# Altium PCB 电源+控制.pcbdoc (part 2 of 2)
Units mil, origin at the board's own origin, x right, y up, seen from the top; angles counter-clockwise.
Board outline 7045 x 4395 mil, 2 copper layers (Top Layer, Bottom Layer); 84 components, 54 nets, 254 pads, 98 vias.
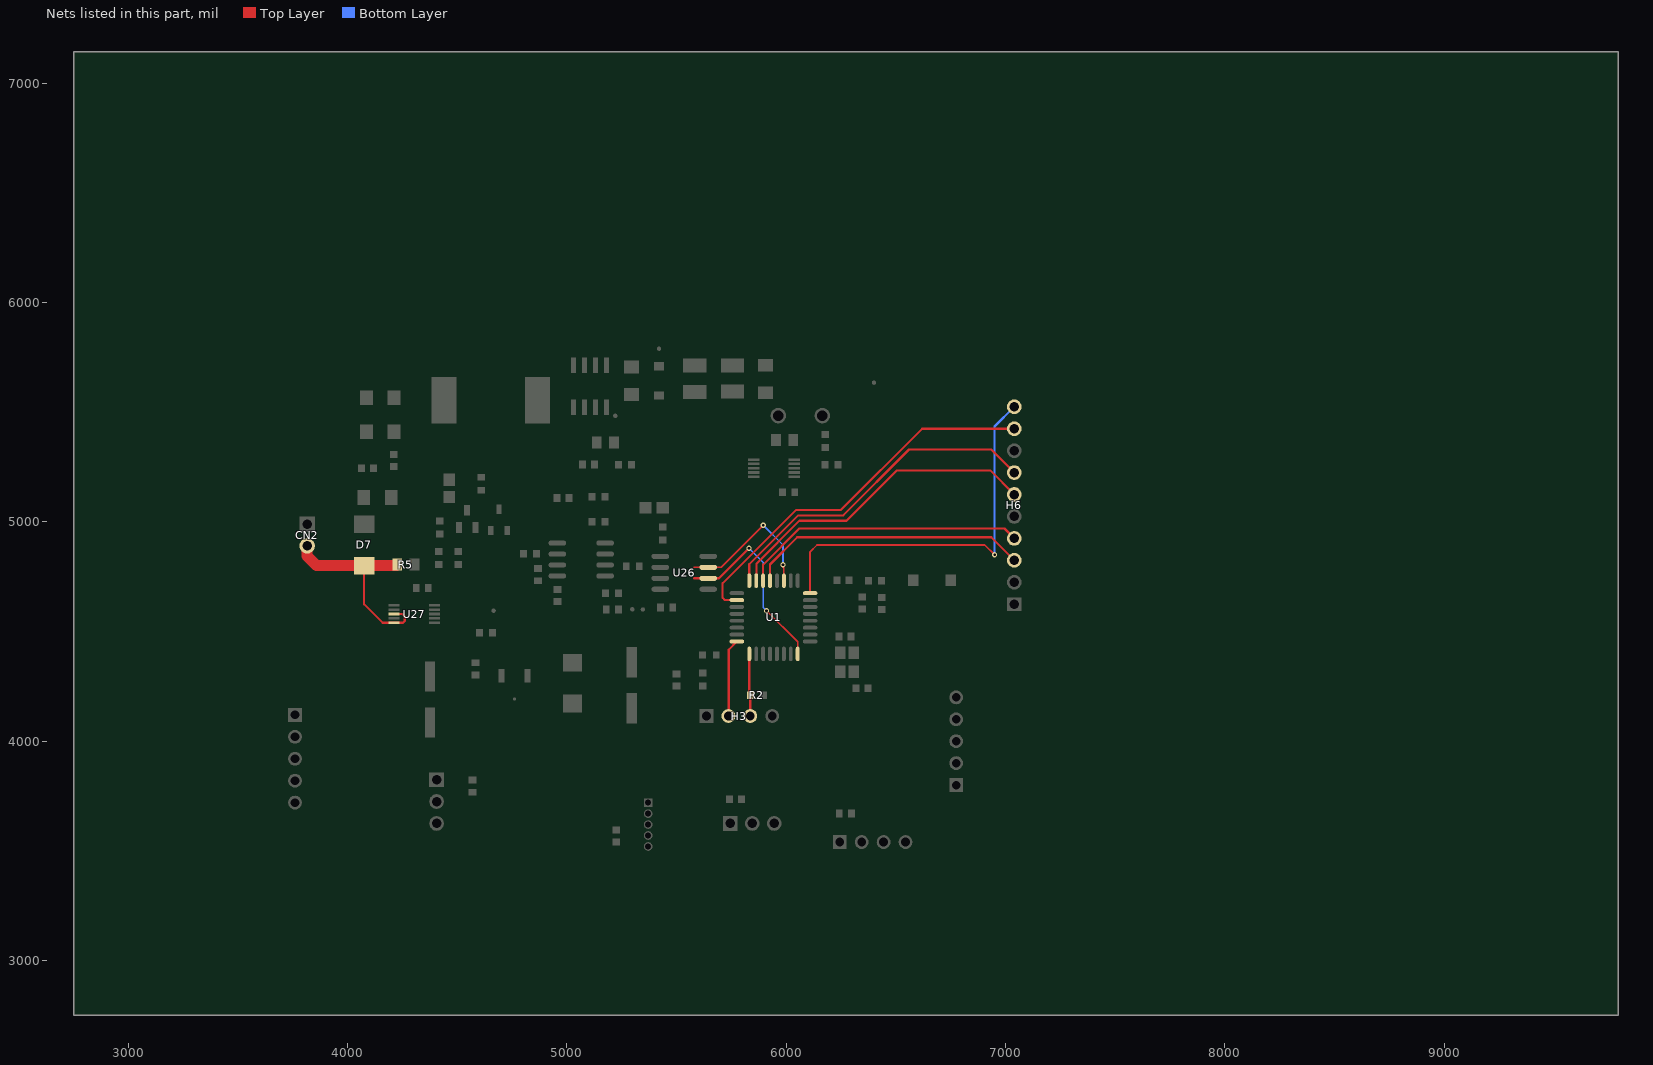
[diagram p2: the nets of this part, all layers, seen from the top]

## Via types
v1: diameter 24.02, hole 12.01, Top Layer to Bottom Layer, 98 vias

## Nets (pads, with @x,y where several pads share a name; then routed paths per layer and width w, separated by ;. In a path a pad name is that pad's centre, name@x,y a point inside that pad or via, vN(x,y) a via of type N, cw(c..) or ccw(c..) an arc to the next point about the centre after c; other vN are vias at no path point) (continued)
SPI_MOSI: U1.11 U26.3 | length 684.4
  Top Layer w8: 5579.15,4792.96 U26.3@5644.15,4792.96 5702.96,4792.96 v1(5895,4985) ; v1@5980,4800 5989.13,4790.87 U1.11@5989.13,4732.01
  Bottom Layer w8: v1(5895,4985) 5985,4895 v1(5985,4805)
SPI_SCK: U1.32 U26.2 | length 881.6
  Top Layer w8: v1(5910,4595) 6052.13,4452.87 U1.32@6052.13,4397.99
  Top Layer w10: 5579.15,4742.96 5624.15,4742.96 5692.96,4742.96 v1(5830,4880)
  Bottom Layer w8: v1(5830,4880) 5895,4815 5895,4610 v1(5910,4595)
SWCLK: H3.3 R2.2 U1.25 | length 284.8
  Top Layer w10: U1.25@5831.65,4397.99 5831.65,4214.42 R2.2@5836.08,4210 H3.3@5836.08,4115
SWDIO: H3.2 U1.24 | length 350.1
  Top Layer w10: H3.2@5737.77,4120 5737.77,4417.64 U1.24@5774.88,4454.76
SWITCH1: H6.3 U1.13 | length 1282.8
  Top Layer w10: U1.13@5926.14,4732.01 5926.14,4806.14 6050,4930 6935,4930 H6.3@7040,4825
SWITCH2: H6.4 U1.14 | length 1305.1
  Top Layer w10: U1.14@5894.65,4732.01 5894.65,4804.65 6060,4970 6995,4970 H6.4@7040,4925
SWITCH3: H6.6 U1.15 | length 1475.4
  Top Layer w10: U1.15@5863.15,4732.01 5865,4733.86 5865,4810 6060,5005 6275,5005 6505,5235 6930,5235 H6.6@7040,5125
SWITCH4: H6.7 U1.16 | length 1543.3
  Top Layer w10: U1.16@5831.65,4732.01 5831.65,4806.65 6055,5030 6260,5030 6560,5330 6935,5330 H6.7@7040,5225
SWITCH5: H6.9 U1.18 | length 1757.3
  Top Layer w10: U1.18@5774.88,4643.74 5720,4643.74 5710,4653.74 5710,4720 6045,5055 6250,5055 6620,5425 H6.9@7040,5425
SWITCH6: H6.10 U1.8 | length 1773.6
  Top Layer w8: U1.8@6108.9,4675.24 6108.9,4863.9 6140,4895 6905,4895 v1(6950,4850)
  Bottom Layer w10: v1(6950,4850) 6950,5435 H6.10@7040,5525
VBUS: CN2.2 D7.1 R5.2 U27.8 U27.10 | length 921.8
  Top Layer w10: D7.1@4073.22,4802.06 4075,4800.28 4075,4625 4159.38,4540.62 U27.10@4211.06,4540.62 4252.48,4540.62 4260,4548.14 4260,4570 4249.99,4580.01 U27.8@4211.06,4580.01
  Top Layer w50: CN2.2@3815,4865.79 3815,4845 3857.94,4802.06 4073.22,4802.06 R5.2@4222.44,4802.06
pads on no net: D6.2 OSC1.1 U27.3 U28.3

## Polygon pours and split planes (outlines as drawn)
PGND on Top Layer (solid, remove dead copper, pour order 6): 3015,6155 7730,6155 7730,3270 3015,3270
PGND on Bottom Layer (solid, remove dead copper, pour order 14): 3000,6245 7715,6245 7715,3360 3000,3360
GND on Top Layer (solid, remove dead copper, pour order 0): 6150.53,4877.34 6844.28,4877.34 6880,4844.01 6880,4510 7260.09,4510 7255.48,3929.7 7255.48,3492.05 7255,3415 5645,3425 5635,3415 5635,3550 5640,3555 5869.85,3555 5889.85,3575 5889.85,3680.14 5875,3695 5770,3695 5765,3700 5765,3795 5795,3825 6233.61,3825 6326.57,3732.05 6829.83,3732.05 6829.83,4145 6429.31,4145 6429.31,4525.28 6150.53,4525.28
GND on Bottom Layer (solid, remove dead copper, pour order 8): 3615,3770 4640,3770 4720,3850 4720,4504.14 5570,4504.14 5570,4055 5600,4025 5885,4025 5885,4265 6111.71,4265 6111.71,4536.39 7289.11,4537.3 7290,3375 3635,3375 3620,3360 3620,3760 3615,3765
GND on Top Layer (solid, remove dead copper, pour order 4): 4975,5150 4975,5070 4985,5060 5015,5060 5015,4890 5005,4880 4770,4880 4770,4775 4785,4760 4879.42,4760 4900,4739.42 4900,4665 5000,4665 5040,4705 5129.34,4705 5129.34,4565.66 5150,4545 5454.39,4545 5454.39,4670 5505,4670 5505,4922.8 5562.2,4980 5710,4980 5960,5230 6009.76,5230 6009.76,5064.76 5759.69,4814.69 5589.9,4814.69 5589.9,4650 5719.9,4520 5725,4520 5725,4450 5715,4440 5645,4440 5640,4435 5640,4285.32 5363.53,4285.32 4868.2,4260.46 4801.3,4260.46 4801.3,4347.84 4635,4347.84 4635,4890 4680,4935 4760,4935 4760,5150

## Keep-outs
Top Layer:
  region: 5321.6,4788.93 5406.07,4788.93 5410,4785 5410,4690 5450.31,4649.69 5450.31,4560 5146.22,4560 5146.22,4641.22 5308.78,4641.22 5308.78,4778.68 5321.46,4791.35 5321.46,4789.07
  region: 5210,5105 5352.92,5105 5363.59,5094.34 5363.59,4806.57 5355.14,4798.12 5195.77,4798.12 5190.34,4803.56 5190.34,5085.34
  region: 5790,5200 5920,5200 5705,4985 5590,4985 5585,4990 5790,5195
  region: 4895,3560 4895,3460 5400,3460 5420,3480 5420,3575 4910,3575
  region: 4165,4875 4275,4875 4275,4755 4290,4740 4290,4629.31 4304.59,4614.72 4393.22,4614.72 4408.26,4599.69 4395.43,4586.86 4395.43,4482.34 4435,4420 4290,4475 4259.59,4505.41 4259.59,4530.21 4207.92,4581.88 4118.12,4581.88 4075,4625 4075,4785
  region: 6612.64,5417.64 6220,5025 6220,4990 6315,4895 6929.23,4895 6995,4829.23 6995,4665 6990,4660 7080,4660 7090,4670 7090,5644.22 6995,5644.22 6995,5440 6990,5435 6630,5435
Bottom Layer:
  region: 4675,4685 4715,4685 4715,4650 4675,4650
  region: 6140,5460 6230.13,5460 6230.13,5401.5 6140,5401.5
  region: 7063.18,5645 7175,5645 7260,5560 7260,4545 6760,4545 6820,5300
  region: 5905,4675 5965,4675 5985,4655 5985,4597.82 6025,4557.82 5969.6,4502.41 5960,4502.41 5960,4620
  region: 4410,5045 4365,5045 4350,5030 4350,5025 4402.39,4972.61 4410,4980.22
Board Outline Layer:
  circle w1: c3970,4445 r137.8
  region: 4107.8,4445 cw(c3970,4445) 3832.2,4445 cw(c3970,4445)
  region: 4340,5815 4955,5815 4955,5275 4340,5275
  lines w10: 6948.82,3480 3650,3480 3650,5880 6954.34,5880 ; 6948.96,3480 6948.96,3717.03 7190,3717.03 7190,5644.3 6955,5644.3 6955,5880

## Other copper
Top Layer:
  drawing of 279 lines, arcs and shapes, not listed
  text "上下翻转，右边放排针，下面放蓝牙红外线和雷达，中间放芯片，左边放电源" at 7505,6775 h120
  text "信号" at 4350,3000 h120
Bottom Layer:
  region net DS3231: 3803.5,4116.06 3803.5,4124.06 cw(c3803.5,4139.06) 3791.5,4130.06 3791.5,4110.06 cw(c3803.5,4101.06)
  region net +3.3V: 6249.12,3586.5 6239.12,3586.5 cw(c6220.37,3586.5) 6231.62,3571.5 6256.62,3571.5 cw(c6267.87,3586.5)
  region net BLE_TX: 6377.27,3567.49 6371.61,3573.15 6371.09,3572.68 6370.5,3572.27 6369.85,3571.91 6369.14,3571.59 6368.39,3571.32 6367.58,3571.08 6365.84,3570.73 6363.94,3570.52 6361.94,3570.42 6358.77,3570.45 6349.14,3571.16 6344.46,3571.46 6342.87,3571.47 6342.15,3571.43 6375.55,3538.03 6375.59,3539.52 6375.43,3543.05 6374.62,3553.57 6374.53,3556.78 6374.58,3558.83 6374.73,3560.79 6375.01,3562.61 6375.2,3563.46 6375.43,3564.27 6375.71,3565.02 6376.03,3565.73 6376.39,3566.38 6376.8,3566.97
  region net BLE_RX: 6477.27,3567.49 6471.61,3573.15 6471.09,3572.68 6470.5,3572.27 6469.85,3571.91 6469.14,3571.59 6468.39,3571.32 6467.58,3571.08 6465.84,3570.73 6463.94,3570.52 6461.94,3570.42 6458.77,3570.45 6449.14,3571.16 6444.46,3571.46 6442.87,3571.47 6442.15,3571.43 6475.55,3538.03 6475.59,3539.52 6475.43,3543.05 6474.62,3553.57 6474.53,3556.78 6474.58,3558.83 6474.73,3560.79 6475.01,3562.61 6475.2,3563.46 6475.43,3564.27 6475.71,3565.02 6476.03,3565.73 6476.39,3566.38 6476.8,3566.97
  region net +3.3V: 5643.58,4161.08 5628.58,4161.08 cw(c5613.5,4161.08) 5617.33,4146.5 5654.83,4146.5 cw(c5658.65,4161.08)
  region net +3.3V: 5672.88,4067.59 5683.48,4078.2 cw(c5723.26,4117.98) 5667.57,4110.02 5641.06,4083.5 cw(c5633.1,4027.82)
  region net LIGHT_ADC: 4450.92,3621 4450.92,3629 4450.17,3629.05 4449.41,3629.18 4448.64,3629.4 4447.87,3629.69 4447.09,3630.06 4446.31,3630.5 4445.53,3631 4443.95,3632.17 4442.37,3633.54 4440.01,3635.88 4436.18,3640.22 4429.89,3647.68 4428.07,3649.57 4427.5,3650.1 4427.5,3599.9 4428.66,3601.01 4430.54,3603.05 4437.69,3611.56 4440.8,3614.93 4442.37,3616.46 4443.95,3617.83 4445.53,3619 4446.31,3619.5 4447.09,3619.94 4447.87,3620.31 4448.64,3620.6 4449.41,3620.82 4450.17,3620.95
  region net INFRARED-RAY: 5849,3665 5841,3665 5840.95,3664.26 5840.82,3663.55 5840.6,3662.86 5840.31,3662.19 5839.94,3661.54 5839.5,3660.9 5839,3660.29 5838.45,3659.69 5837.83,3659.1 5836.46,3657.97 5834.93,3656.88 5832.43,3655.32 5825.42,3651.33 5823.05,3649.81 5821.64,3648.77 5821.01,3648.23 5820.43,3647.69 5819.9,3647.13 5870.1,3647.13 5869.57,3647.69 5868.99,3648.23 5867.68,3649.29 5866.19,3650.32 5862.87,3652.32 5856.71,3655.83 5854.28,3657.42 5852.83,3658.53 5852.17,3659.1 5851.55,3659.69 5851,3660.29 5850.5,3660.9 5850.06,3661.54 5849.69,3662.19 5849.4,3662.86 5849.18,3663.55 5849.05,3664.26
  region net 170V: 6213.04,5470 6213.04,5500 6211.39,5500.07 6209.73,5500.26 6208.07,5500.57 6206.4,5500.99 6204.73,5501.52 6202.26,5502.48 6199.82,5503.62 6197.44,5504.91 6195.14,5506.33 6192.21,5508.36 6189.5,5510.49 6188.24,5511.57 6188.24,5458.43 6190.83,5460.58 6193.65,5462.68 6196.66,5464.63 6199.02,5465.97 6201.44,5467.16 6203.9,5468.18 6205.56,5468.76 6207.23,5469.23 6208.9,5469.6 6210.56,5469.85 6212.22,5469.98
  region net SWITCH6: 7004.25,5496.32 7011.32,5489.25 7012.79,5490.63 7013.74,5491.41 7014.66,5492.09 7015.55,5492.67 7016.42,5493.16 7017.27,5493.56 7018.11,5493.88 7018.94,5494.13 7019.76,5494.3 7020.57,5494.41 7021.38,5494.46 7022.18,5494.45 7022.99,5494.4 7024.22,5494.25 7025.89,5493.92 7031.38,5492.57 7033.99,5492.04 7036.26,5491.73 7038.09,5491.58 7040.03,5491.53 7042.1,5491.6 7006.6,5527.1 7006.53,5525.03 7006.58,5523.09 7006.73,5521.26 7007.04,5518.99 7007.57,5516.38 7008.92,5510.89 7009.25,5509.22 7009.4,5507.99 7009.45,5507.18 7009.46,5506.38 7009.41,5505.57 7009.3,5504.76 7009.13,5503.94 7008.88,5503.11 7008.56,5502.27 7008.16,5501.42 7007.67,5500.55 7007.09,5499.66 7006.41,5498.74 7005.63,5497.79
  region net COLON2: 7068.68,5289.25 7075.75,5296.32 7074.37,5297.79 7073.59,5298.74 7072.91,5299.66 7072.33,5300.55 7071.84,5301.42 7071.44,5302.27 7071.12,5303.11 7070.87,5303.94 7070.7,5304.76 7070.59,5305.57 7070.54,5306.38 7070.55,5307.18 7070.6,5307.99 7070.75,5309.22 7071.08,5310.89 7072.43,5316.38 7072.96,5318.99 7073.27,5321.26 7073.42,5323.09 7073.47,5325.03 7073.4,5327.1 7037.9,5291.6 7039.97,5291.53 7041.91,5291.58 7043.74,5291.73 7046.01,5292.04 7048.62,5292.57 7054.11,5293.92 7055.78,5294.25 7057.01,5294.4 7057.82,5294.45 7058.62,5294.46 7059.43,5294.41 7060.24,5294.3 7061.06,5294.13 7061.89,5293.88 7062.73,5293.56 7063.58,5293.16 7064.45,5292.67 7065.34,5292.09 7066.26,5291.41 7067.21,5290.63
  region net COLON1: 7068.68,4989.25 7075.75,4996.32 7074.37,4997.79 7073.59,4998.74 7072.91,4999.66 7072.33,5000.55 7071.84,5001.42 7071.44,5002.27 7071.12,5003.11 7070.87,5003.94 7070.7,5004.76 7070.59,5005.57 7070.54,5006.38 7070.55,5007.18 7070.6,5007.99 7070.75,5009.22 7071.08,5010.89 7072.43,5016.38 7072.96,5018.99 7073.27,5021.26 7073.42,5023.09 7073.47,5025.03 7073.4,5027.1 7037.9,4991.6 7039.97,4991.53 7041.91,4991.58 7043.74,4991.73 7046.01,4992.04 7048.62,4992.57 7054.11,4993.92 7055.78,4994.25 7057.01,4994.4 7057.82,4994.45 7058.62,4994.46 7059.43,4994.41 7060.24,4994.3 7061.06,4994.13 7061.89,4993.88 7062.73,4993.56 7063.58,4993.16 7064.45,4992.67 7065.34,4992.09 7066.26,4991.41 7067.21,4990.63
  region net 170V: 6994.44,4740 6994.44,4710 6995.9,4709.94 6997.4,4709.77 6998.95,4709.5 7000.52,4709.13 7002.9,4708.42 7005.29,4707.52 7007.65,4706.48 7009.95,4705.32 7012.16,4704.05 7014.23,4702.71 7016.15,4701.32 7017.87,4699.9 7017.87,4750.1 7016.15,4748.68 7014.23,4747.29 7012.16,4745.95 7009.95,4744.68 7007.65,4743.52 7005.29,4742.48 7002.9,4741.58 7000.52,4740.87 6998.95,4740.5 6997.4,4740.23 6995.9,4740.06
  region net +5V: 6724.5,4089.85 6738.65,4075.71 6739.06,4076.1 6739.48,4076.45 6739.91,4076.76 6740.36,4077.04 6740.82,4077.29 6741.29,4077.5 6741.77,4077.69 6742.26,4077.84 6742.77,4077.97 6743.28,4078.06 6743.8,4078.13 6744.88,4078.2 6745.99,4078.16 6747.13,4078.04 6748.3,4077.84 6750.11,4077.4 6751.98,4076.82 6755.18,4075.62 6764.44,4071.62 6767.73,4070.33 6770.31,4069.49 6772.2,4069.01 6773.43,4068.77 6774.64,4068.61 6775.82,4068.54 6776.97,4068.57 6743.57,4101.97 6743.49,4101.35 6743.33,4100.75 6743.11,4100.2 6742.82,4099.67 6742.47,4099.18 6742.06,4098.71 6741.6,4098.27 6741.09,4097.86 6740.53,4097.47 6739.3,4096.74 6737.93,4096.07 6735.7,4095.16 6730.23,4093.14 6728.04,4092.19 6726.71,4091.49 6726.09,4091.12 6725.52,4090.72 6724.99,4090.3
  region net I2C1_SDA: 4453.02,4574.9 4460.1,4581.98 4459.71,4582.39 4459.35,4582.84 4459.03,4583.32 4458.73,4583.83 4458.46,4584.35 4458,4585.46 4457.64,4586.62 4457.36,4587.81 4457.16,4589 4456.98,4590.75 4444.25,4578.02 4446,4577.84 4447.19,4577.64 4448.38,4577.36 4449.54,4577 4450.65,4576.54 4451.17,4576.27 4451.68,4575.97 4452.16,4575.65 4452.61,4575.29
  region net I2C1_SCL: 4461.35,4635 4461.35,4645 4460.78,4645.02 4460.21,4645.09 4459.64,4645.2 4459.08,4645.34 4458.51,4645.53 4457.41,4645.98 4456.33,4646.54 4455.29,4647.19 4454.3,4647.89 4452.94,4649.01 4452.94,4630.99 4454.3,4632.11 4455.29,4632.81 4456.33,4633.46 4457.41,4634.02 4458.51,4634.47 4459.08,4634.66 4459.64,4634.8 4460.21,4634.91 4460.78,4634.98
  region net I2C1_SCL: 5701.98,4630.1 5694.9,4623.02 5695.29,4622.61 5695.65,4622.16 5695.97,4621.68 5696.27,4621.17 5696.54,4620.65 5697,4619.54 5697.36,4618.38 5697.64,4617.19 5697.84,4616 5698.02,4614.25 5710.75,4626.98 5709,4627.16 5707.81,4627.36 5706.62,4627.64 5705.46,4628 5704.35,4628.46 5703.83,4628.73 5703.32,4629.03 5702.84,4629.35 5702.39,4629.71
  region net I2C1_SCL: 5730.05,4618.07 5724.39,4623.73 5723.7,4623.2 5722.94,4622.89 5722.12,4622.77 5721.25,4622.82 5720.32,4623.01 5719.36,4623.31 5717.35,4624.17 5713.19,4626.12 5712.17,4626.5 5711.16,4626.79 5710.19,4626.96 5709.25,4626.98 5721.98,4614.25 5722.3,4615.17 5723.03,4615.79 5724.07,4616.2 5726.63,4616.72 5727.93,4617.01 5729.11,4617.43
  region net I2C1_SDA: 5693.65,4550 5693.65,4540 5694.22,4539.98 5694.79,4539.91 5695.36,4539.8 5695.92,4539.66 5696.49,4539.47 5697.59,4539.02 5698.67,4538.46 5699.71,4537.81 5700.7,4537.11 5702.06,4535.99 5702.06,4554.01 5700.7,4552.89 5699.71,4552.19 5698.67,4551.54 5697.59,4550.98 5696.49,4550.53 5695.92,4550.34 5695.36,4550.2 5694.79,4550.09 5694.22,4550.02
  region net I2C1_SDA: 5721.89,4556.23 5716.23,4561.89 5714.23,4559.74 5713.49,4558.97 5713.11,4558.62 5712.72,4558.3 5712.31,4558 5711.88,4557.74 5711.42,4557.5 5710.94,4557.31 5710.42,4557.16 5709.85,4557.05 5709.25,4556.98 5721.98,4544.25 5721.99,4544.89 5721.94,4545.59 5721.73,4547.16 5721.16,4550.59 5720.97,4552.29 5720.94,4553.09 5720.97,4553.85 5721.07,4554.55 5721.25,4555.19 5721.52,4555.76
  region net SWITCH6: 6955,4866.35 6945,4866.35 6944.98,4865.78 6944.91,4865.21 6944.8,4864.64 6944.66,4864.08 6944.47,4863.51 6944.02,4862.41 6943.46,4861.33 6942.81,4860.29 6942.11,4859.3 6940.99,4857.94 6959.01,4857.94 6957.89,4859.3 6957.19,4860.29 6956.54,4861.33 6955.98,4862.41 6955.53,4863.51 6955.34,4864.08 6955.2,4864.64 6955.09,4865.21 6955.02,4865.78
  region net COLON2: 6685,4141.35 6675,4141.35 6674.98,4140.78 6674.91,4140.21 6674.8,4139.64 6674.66,4139.08 6674.47,4138.51 6674.02,4137.41 6673.46,4136.33 6672.81,4135.29 6672.11,4134.3 6670.99,4132.94 6689.01,4132.94 6687.89,4134.3 6687.19,4135.29 6686.54,4136.33 6685.98,4137.41 6685.53,4138.51 6685.34,4139.08 6685.2,4139.64 6685.09,4140.21 6685.02,4140.78
  region net POWER: 5754.9,4711.98 5761.98,4704.9 5762.57,4705.37 5763.25,4705.66 5763.99,4705.81 5764.79,4705.82 5765.64,4705.73 5766.53,4705.54 5768.41,4704.97 5772.25,4703.62 5773.18,4703.35 5774.08,4703.14 5774.94,4703.03 5775.75,4703.02 5763.02,4715.75 5762.7,4714.82 5761.97,4714.21 5760.92,4713.81 5758.35,4713.31 5757.03,4713.03 5755.85,4712.62
  region net POWER: 4378.02,4989.9 4385.1,4996.98 4384.71,4997.39 4384.35,4997.84 4384.03,4998.32 4383.73,4998.83 4383.46,4999.35 4383,5000.46 4382.64,5001.62 4382.36,5002.81 4382.16,5004 4381.98,5005.75 4369.25,4993.02 4371,4992.84 4372.19,4992.64 4373.38,4992.36 4374.54,4992 4375.65,4991.54 4376.17,4991.27 4376.68,4990.97 4377.16,4990.65 4377.61,4990.29
  region net +5V: 4828.02,4769.9 4835.1,4776.98 4834.71,4777.39 4834.35,4777.84 4834.03,4778.32 4833.73,4778.83 4833.46,4779.35 4833,4780.46 4832.64,4781.62 4832.36,4782.81 4832.16,4784 4831.98,4785.75 4819.25,4773.02 4821,4772.84 4822.19,4772.64 4823.38,4772.36 4824.54,4772 4825.65,4771.54 4826.17,4771.27 4826.68,4770.97 4827.16,4770.65 4827.61,4770.29
  region net BLE_TX: 6069.39,4813.73 6063.73,4819.39 6063.23,4818.92 6062.71,4818.53 6062.19,4818.19 6061.65,4817.92 6061.11,4817.69 6060.55,4817.51 6059.98,4817.38 6059.4,4817.27 6058.2,4817.14 6054.95,4817.02 6054.25,4816.98 6066.98,4804.25 6067.11,4807.58 6067.2,4808.81 6067.27,4809.4 6067.38,4809.98 6067.51,4810.55 6067.69,4811.11 6067.92,4811.65 6068.19,4812.19 6068.53,4812.71 6068.92,4813.23
  region net BLE_RX: 6034.39,4813.73 6028.73,4819.39 6028.23,4818.92 6027.71,4818.53 6027.19,4818.19 6026.65,4817.92 6026.11,4817.69 6025.55,4817.51 6024.98,4817.38 6024.4,4817.27 6023.2,4817.14 6019.95,4817.02 6019.25,4816.98 6031.98,4804.25 6032.11,4807.58 6032.2,4808.81 6032.27,4809.4 6032.38,4809.98 6032.51,4810.55 6032.69,4811.11 6032.92,4811.65 6033.19,4812.19 6033.53,4812.71 6033.92,4813.23
  region net SPI_MOSI: 5989,4821.35 5981,4821.35 5980.97,4820.66 5980.89,4820.02 5980.75,4819.41 5980.57,4818.84 5980.34,4818.29 5980.08,4817.77 5979.77,4817.27 5979.44,4816.79 5978.68,4815.85 5976.46,4813.46 5975.99,4812.94 5994.01,4812.94 5991.74,4815.39 5990.93,4816.32 5990.56,4816.79 5990.23,4817.27 5989.92,4817.77 5989.66,4818.29 5989.43,4818.84 5989.25,4819.41 5989.11,4820.02 5989.03,4820.66
  region net SPI_MOSI: 5903.73,4970.61 5909.39,4976.27 5908.92,4976.77 5908.53,4977.29 5908.19,4977.81 5907.92,4978.35 5907.69,4978.89 5907.51,4979.45 5907.38,4980.02 5907.27,4980.6 5907.14,4981.8 5907.02,4985.05 5906.98,4985.75 5894.25,4973.02 5897.58,4972.89 5898.81,4972.8 5899.4,4972.73 5899.98,4972.62 5900.55,4972.49 5901.11,4972.31 5901.65,4972.08 5902.19,4971.81 5902.71,4971.47 5903.23,4971.08
  region net SPI_SCK: 5838.73,4865.61 5844.39,4871.27 5843.92,4871.77 5843.53,4872.29 5843.19,4872.81 5842.92,4873.35 5842.69,4873.89 5842.51,4874.45 5842.38,4875.02 5842.27,4875.6 5842.14,4876.8 5842.02,4880.05 5841.98,4880.75 5829.25,4868.02 5832.58,4867.89 5833.81,4867.8 5834.4,4867.73 5834.98,4867.62 5835.55,4867.49 5836.11,4867.31 5836.65,4867.08 5837.19,4866.81 5837.71,4866.47 5838.23,4866.08
  region net SPI_SCK: 5901.27,4609.39 5895.61,4603.73 5896.08,4603.23 5896.47,4602.71 5896.81,4602.19 5897.08,4601.65 5897.31,4601.11 5897.49,4600.55 5897.62,4599.98 5897.73,4599.4 5897.86,4598.2 5897.98,4594.95 5898.02,4594.25 5910.75,4606.98 5907.42,4607.11 5906.19,4607.2 5905.6,4607.27 5905.02,4607.38 5904.45,4607.51 5903.89,4607.69 5903.35,4607.92 5902.81,4608.19 5902.29,4608.53 5901.77,4608.92
  region net I2C1_SCL: 5603.73,5000.61 5609.39,5006.27 5608.92,5006.77 5608.53,5007.29 5608.19,5007.81 5607.92,5008.35 5607.69,5008.89 5607.51,5009.45 5607.38,5010.02 5607.27,5010.6 5607.14,5011.8 5607.02,5015.05 5606.98,5015.75 5594.25,5003.02 5597.58,5002.89 5598.81,5002.8 5599.4,5002.73 5599.98,5002.62 5600.55,5002.49 5601.11,5002.31 5601.65,5002.08 5602.19,5001.81 5602.71,5001.47 5603.23,5001.08
  region net I2C1_SDA: 5616,5073.65 5624,5073.65 5624.03,5074.34 5624.11,5074.98 5624.25,5075.59 5624.43,5076.16 5624.66,5076.71 5624.92,5077.23 5625.23,5077.73 5625.56,5078.21 5626.32,5079.15 5628.54,5081.54 5629.01,5082.06 5610.99,5082.06 5613.26,5079.61 5614.07,5078.68 5614.44,5078.21 5614.77,5077.73 5615.08,5077.23 5615.34,5076.71 5615.57,5076.16 5615.75,5075.59 5615.89,5074.98 5615.97,5074.34
  region net DS3231: 5831.27,4494.39 5825.61,4488.73 5826.08,4488.23 5826.47,4487.71 5826.81,4487.19 5827.08,4486.65 5827.31,4486.11 5827.49,4485.55 5827.62,4484.98 5827.73,4484.4 5827.86,4483.2 5827.98,4479.95 5828.02,4479.25 5840.75,4491.98 5837.42,4492.11 5836.19,4492.2 5835.6,4492.27 5835.02,4492.38 5834.45,4492.51 5833.89,4492.69 5833.35,4492.92 5832.81,4493.19 5832.29,4493.53 5831.77,4493.92
  region net RADER_TX: 5956,4648.65 5964,4648.65 5964.03,4649.34 5964.11,4649.98 5964.25,4650.59 5964.43,4651.16 5964.66,4651.71 5964.92,4652.23 5965.23,4652.73 5965.56,4653.21 5966.32,4654.15 5968.54,4656.54 5969.01,4657.06 5950.99,4657.06 5953.26,4654.61 5954.07,4653.68 5954.44,4653.21 5954.77,4652.73 5955.08,4652.23 5955.34,4651.71 5955.57,4651.16 5955.75,4650.59 5955.89,4649.98 5955.97,4649.34
  region net RADER_TX: 5544.39,4128.73 5538.73,4134.39 5538.4,4133.99 5538.1,4133.53 5537.84,4133.01 5537.39,4131.86 5536.57,4129.45 5536.34,4128.9 5536.09,4128.39 5535.81,4127.94 5535.49,4127.57 5535.13,4127.27 5534.72,4127.07 5534.25,4126.98 5546.98,4114.25 5546.97,4115.13 5546.82,4116.05 5546.57,4117 5545.86,4118.98 5544.2,4122.97 5543.87,4123.93 5543.62,4124.86 5543.47,4125.75 5543.45,4126.59 5543.58,4127.37 5543.89,4128.09
  region net RADER: 6054,4111.35 6046,4111.35 6045.97,4110.66 6045.89,4110.02 6045.75,4109.41 6045.57,4108.84 6045.34,4108.29 6045.08,4107.77 6044.77,4107.27 6044.44,4106.79 6043.68,4105.85 6041.46,4103.46 6040.99,4102.94 6059.01,4102.94 6056.74,4105.39 6055.93,4106.32 6055.56,4106.79 6055.23,4107.27 6054.92,4107.77 6054.66,4108.29 6054.43,4108.84 6054.25,4109.41 6054.11,4110.02 6054.03,4110.66
  region net RADER_RX: 6094,4086.35 6086,4086.35 6085.97,4085.66 6085.89,4085.02 6085.75,4084.41 6085.57,4083.84 6085.34,4083.29 6085.08,4082.77 6084.77,4082.27 6084.44,4081.79 6083.68,4080.85 6081.46,4078.46 6080.99,4077.94 6099.01,4077.94 6096.74,4080.39 6095.93,4081.32 6095.56,4081.79 6095.23,4082.27 6094.92,4082.77 6094.66,4083.29 6094.43,4083.84 6094.25,4084.41 6094.11,4085.02 6094.03,4085.66
  region net RADER_RX: 6086,4368.65 6094,4368.65 6094.03,4369.34 6094.11,4369.98 6094.25,4370.59 6094.43,4371.16 6094.66,4371.71 6094.92,4372.23 6095.23,4372.73 6095.56,4373.21 6096.32,4374.15 6098.54,4376.54 6099.01,4377.06 6080.99,4377.06 6083.26,4374.61 6084.07,4373.68 6084.44,4373.21 6084.77,4372.73 6085.08,4372.23 6085.34,4371.71 6085.57,4371.16 6085.75,4370.59 6085.89,4369.98 6085.97,4369.34
  region net RADER: 6046,4498.65 6054,4498.65 6053.97,4499.4 6053.89,4500.09 6053.76,4500.72 6053.44,4501.83 6052.96,4503.25 6052.85,4503.69 6052.78,4504.12 6052.77,4504.56 6052.83,4505.01 6052.97,4505.47 6053.21,4505.96 6053.55,4506.49 6054.01,4507.06 6035.99,4507.06 6036.52,4506.54 6037.14,4506.04 6038.61,4505.08 6041.94,4503.21 6043.49,4502.23 6044.18,4501.71 6044.79,4501.16 6045.29,4500.59 6045.67,4499.98 6045.92,4499.34
  region net INFRARED-RAY: 5906,4503.65 5914,4503.65 5914.03,4504.34 5914.11,4504.98 5914.25,4505.59 5914.43,4506.16 5914.66,4506.71 5914.92,4507.23 5915.23,4507.73 5915.56,4508.21 5916.32,4509.15 5918.54,4511.54 5919.01,4512.06 5900.99,4512.06 5903.26,4509.61 5904.07,4508.68 5904.44,4508.21 5904.77,4507.73 5905.08,4507.23 5905.34,4506.71 5905.57,4506.16 5905.75,4505.59 5905.89,4504.98 5905.97,4504.34
  region net LIGHT_ADC: 5848.73,4535.61 5854.39,4541.27 5853.92,4541.77 5853.53,4542.29 5853.19,4542.81 5852.92,4543.35 5852.69,4543.89 5852.51,4544.45 5852.38,4545.02 5852.27,4545.6 5852.14,4546.8 5852.02,4550.05 5851.98,4550.75 5839.25,4538.02 5842.58,4537.89 5843.81,4537.8 5844.4,4537.73 5844.98,4537.62 5845.55,4537.49 5846.11,4537.31 5846.65,4537.08 5847.19,4536.81 5847.71,4536.47 5848.23,4536.08
  region net +3.3V: 6028.65,4557.5 6028.65,4542.5 6031.58,4542.6 6032.65,4542.6 6033.17,4542.58 6033.68,4542.53 6034.18,4542.44 6034.67,4542.32 6035.16,4542.16 6035.64,4541.96 6036.11,4541.69 6036.59,4541.38 6037.06,4540.99 6037.06,4559.01 6036.59,4558.62 6036.11,4558.31 6035.64,4558.04 6035.16,4557.84 6034.67,4557.68 6034.18,4557.56 6033.68,4557.47 6033.17,4557.42 6032.12,4557.39 6029.27,4557.49
  region net +3.3V: 6061.35,4545 6061.35,4555 6060.78,4555.02 6060.21,4555.09 6059.64,4555.2 6059.08,4555.34 6058.51,4555.53 6057.41,4555.98 6056.33,4556.54 6055.29,4557.19 6054.3,4557.89 6052.94,4559.01 6052.94,4540.99 6054.3,4542.11 6055.29,4542.81 6056.33,4543.46 6057.41,4544.02 6058.51,4544.47 6059.08,4544.66 6059.64,4544.8 6060.21,4544.91 6060.78,4544.98
  region net +5V: 6018.65,5180 6018.65,5170 6019.22,5169.98 6019.79,5169.91 6020.36,5169.8 6020.92,5169.66 6021.49,5169.47 6022.59,5169.02 6023.67,5168.46 6024.71,5167.81 6025.7,5167.11 6027.06,5165.99 6027.06,5184.01 6025.7,5182.89 6024.71,5182.19 6023.67,5181.54 6022.59,5180.98 6021.49,5180.53 6020.92,5180.34 6020.36,5180.2 6019.79,5180.09 6019.22,5180.02
  region net +3.3V: 6304.37,4246.5 6304.37,4236.5 6304.91,4236.48 6305.41,4236.41 6305.87,4236.3 6306.29,4236.16 6306.69,4235.98 6307.06,4235.76 6307.41,4235.52 6307.75,4235.25 6308.41,4234.64 6310.16,4232.87 6310.57,4232.5 6310.57,4250.51 6309.77,4249.76 6308.08,4248.05 6307.75,4247.75 6307.41,4247.48 6307.06,4247.24 6306.69,4247.03 6306.29,4246.85 6305.87,4246.7 6305.41,4246.59 6304.91,4246.52
  region net $3N2629: 4681.35,4590 4681.35,4600 4680.78,4600.02 4680.21,4600.09 4679.64,4600.2 4679.08,4600.34 4678.51,4600.53 4677.41,4600.98 4676.33,4601.54 4675.29,4602.19 4674.3,4602.89 4672.94,4604.01 4672.94,4585.99 4674.3,4587.11 4675.29,4587.81 4676.33,4588.46 4677.41,4589.02 4678.51,4589.47 4679.08,4589.66 4679.64,4589.8 4680.21,4589.91 4680.78,4589.98
  region net +3.3V: 6259.9,4646.98 6266.98,4639.9 6267.39,4640.29 6267.84,4640.65 6268.32,4640.97 6268.83,4641.27 6269.35,4641.54 6270.46,4642 6271.62,4642.36 6272.81,4642.64 6274,4642.84 6275.75,4643.02 6263.02,4655.75 6262.84,4654 6262.64,4652.81 6262.36,4651.62 6262,4650.46 6261.54,4649.35 6261.27,4648.83 6260.97,4648.32 6260.65,4647.84 6260.29,4647.39
  region net COLON1: 6650,4106.35 6640,4106.35 6639.98,4105.78 6639.91,4105.21 6639.8,4104.64 6639.66,4104.08 6639.47,4103.51 6639.02,4102.41 6638.46,4101.33 6637.81,4100.29 6637.11,4099.3 6635.99,4097.94 6654.01,4097.94 6652.89,4099.3 6652.19,4100.29 6651.54,4101.33 6650.98,4102.41 6650.53,4103.51 6650.34,4104.08 6650.2,4104.64 6650.09,4105.21 6650.02,4105.78
  region net +5V: 5859.77,5309.9 5866.84,5316.98 5866.46,5317.39 5866.1,5317.84 5865.78,5318.32 5865.48,5318.83 5865.21,5319.35 5864.75,5320.46 5864.39,5321.62 5864.11,5322.81 5863.91,5324 5863.73,5325.75 5851,5313.02 5852.75,5312.84 5853.94,5312.64 5855.13,5312.36 5856.29,5312 5857.4,5311.54 5857.92,5311.27 5858.43,5310.97 5858.91,5310.65 5859.35,5310.29
  region net +3.3V: 6168.65,3677.5 6168.65,3662.5 6171.58,3662.6 6172.65,3662.6 6173.17,3662.58 6173.68,3662.53 6174.18,3662.44 6174.67,3662.32 6175.16,3662.16 6175.64,3661.96 6176.11,3661.69 6176.59,3661.38 6177.06,3660.99 6177.06,3679.01 6176.59,3678.62 6176.11,3678.31 6175.64,3678.04 6175.16,3677.84 6174.67,3677.68 6174.18,3677.56 6173.68,3677.47 6173.17,3677.42 6172.12,3677.39 6169.27,3677.49
  region net +3.3V: 6190,3686.35 6180,3686.35 6179.98,3685.78 6179.91,3685.21 6179.8,3684.64 6179.66,3684.08 6179.47,3683.51 6179.02,3682.41 6178.46,3681.33 6177.81,3680.29 6177.11,3679.3 6175.99,3677.94 6194.01,3677.94 6192.89,3679.3 6192.19,3680.29 6191.54,3681.33 6190.98,3682.41 6190.53,3683.51 6190.34,3684.08 6190.2,3684.64 6190.09,3685.21 6190.02,3685.78
  region net +3.3V: 6193.02,3654.9 6200.1,3661.98 6199.71,3662.39 6199.35,3662.84 6199.03,3663.32 6198.73,3663.83 6198.46,3664.35 6198,3665.46 6197.64,3666.62 6197.36,3667.81 6197.16,3669 6196.98,3670.75 6184.25,3658.02 6186,3657.84 6187.19,3657.64 6188.38,3657.36 6189.54,3657 6190.65,3656.54 6191.17,3656.27 6191.68,3655.97 6192.16,3655.65 6192.61,3655.29
  region net +5V: 5468.65,4720 5468.65,4710 5469.22,4709.98 5469.79,4709.91 5470.36,4709.8 5470.92,4709.66 5471.49,4709.47 5472.59,4709.02 5473.67,4708.46 5474.71,4707.81 5475.7,4707.11 5477.06,4705.99 5477.06,4724.01 5475.7,4722.89 5474.71,4722.19 5473.67,4721.54 5472.59,4720.98 5471.49,4720.53 5470.92,4720.34 5470.36,4720.2 5469.79,4720.09 5469.22,4720.02
  region net $3N2629: 5113.65,4600 5113.65,4590 5114.62,4590.11 5115.72,4590.38 5118.08,4591.09 5119.24,4591.37 5120.33,4591.5 5121.28,4591.4 5122.06,4590.99 5122.06,4609.01 5121.58,4608.53 5121.1,4607.97 5120.15,4606.65 5118.17,4603.66 5117.13,4602.26 5116.6,4601.64 5116.04,4601.09 5115.47,4600.64 5114.89,4600.29 5114.28,4600.08
  region net +3.3V: 6065.59,4545 6065.59,4555 cw(c6065.59,5019.29) 6050.36,4555.25 6050.36,4544.75 cw(c6065.59,4080.71)
  region net +3.3V: 6196.02,3651.91 6203.1,3658.98 cw(c6531.4,3987.28) 6192.5,3669.93 6185.07,3662.5 cw(c5867.72,3323.6)
  region net +3.3V: 6190,3690.59 6180,3692.5 cw(c5729.88,3692.5) 6179.75,3677.5 6190.25,3675.36 cw(c6654.29,3690.59)
  region net +5V: 4837.68,4760.25 4844.75,4767.32 4827.07,4777.93 4795,4795

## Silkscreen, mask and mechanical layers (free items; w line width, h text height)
Top Silkscreen Layer:
  text "C6" at 6240,4510 h45
Mechanical Layer:
  circle w1: c3970,4445 r137.8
